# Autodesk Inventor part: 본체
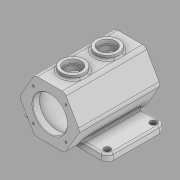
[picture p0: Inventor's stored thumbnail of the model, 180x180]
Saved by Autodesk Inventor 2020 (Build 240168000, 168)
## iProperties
Created: 2021-06
Part Number: 본체
Material: 일반
Document SubType Name: Modeling
Designer: Windows7
Density: 1 g/cm^3
Appearance: 기본값
Mass: 553.834 g
Surface Area: 1102.69 cm^2
Volume: 553.834 cm^3
Author: Windows7
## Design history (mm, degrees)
sketch "스케치1"
  geometry: L1 (75, 50)-(-75, 50); L2 (-75, 50)-(-75, -50); L3 (-75, -50)-(75, -50); L4 (75, -50)-(75, 50); L5 (75, 50)-(-75, -50); L6 (-75, 50)-(75, -50); 1 further point
  constraints: 12 end point, 2 midpoint, 2 parallel, 1 horizontal, 1 perpendicular
  dimensions: "d0" = 150 distance of L3.end L2.end; "d1" = 100 distance of L2.end L1.end
extrude "돌출1" new body sketch "스케치1" distance "d2" = 12; taper "d3" = 0 deg
node "작업 평면1"
sketch "스케치2" dims "d5" = 105
  geometry: L1 (127.5, 50)-(101.25, 4.534); L2 (101.25, 4.534)-(48.75, 4.534); L3 (48.75, 4.534)-(22.5, 50); L4 (22.5, 50)-(48.75, 95.466); L5 (48.75, 95.466)-(101.25, 95.466); L6 (101.25, 95.466)-(127.5, 50); 3 further points
  constraints: 12 end point, 1 coincident, 1 horizontal alignment, 1 vertical alignment, 15 other
  dimensions: "d6" = 50 distance of point (75, 0) point (75, 50); "d7" = 45.46633 vertical distance of L5.end L1.start
extrude "돌출2" join sketch "스케치2" distance "d8" = 140; taper "d9" = 0 deg
sketch "스케치4"
  geometry: L1 (50, 75)-(4.534, 75) reference; L2 (50, 75)-(50, -65); L3 (20, 75)-(20, 63); L4 (20, 63)-(12.5, 63); L5 (12.5, 63)-(12.5, -53); L6 (12, 50)-(12, -50) reference; L7 (12.5, -53)-(20, -53); L8 (20, -53)-(20, -65); 3 further points; 1 other entity
  constraints: 12 end point, 3 perpendicular, 2 vertical, 1 parallel, 1 point on line, 2 other
  dimensions: "d11" = 60 diameter of L3 L2; "d12" = 75 diameter of L5 L2; "d13" = 60 diameter of L8 L2; "d14" = 12 distance of L3.start L3.end; "d15" = 12 distance of L7.end L8.end
revolve "회전1" sketch "스케치4" stored, may be unused: angle "d16" = 90 deg
node "작업 평면4"
sketch "스케치6"
  geometry: L1 (26.25, 75)-(-26.25, 75) reference; C1 r 20 at (0, 35); C2 r 20 at (0, -25); 1 further point
  constraints: 2 centre point, 2 vertical alignment
  dimensions: "d22" = 40 diameter of C1; "d23" = 40 diameter of C2; "d25" = 40 distance from line of C1.centre L1; "d26" = 60 distance of C2.centre C1.centre
extrude "돌출3" join sketch "스케치6" stored distance "d27" = 140; taper "d28" = 0 deg
sketch "스케치7"
  geometry: C1 r 20 at (0, 0) reference; C2 r 20 at (0, 60) reference; 3 further points
  constraints: 2 coincident
hole "구멍1" sketch "스케치7" at (0, 60), (0, 0) diameter "d29" = 25; stored, may be unused: countersink angle "d33" = 90 deg, drill point angle "d35" = 118 deg; dims "d30" = 6, "d31" = 30, "d32" = 8, "d34" = 30
sketch "스케치8"
  geometry: L1 (75, 50)-(75, 90); L2 (75, 50)-(46.716, 78.284); C1 r 37.5 at (75, 50) reference; A1 r 40 centre (75, 50) between (75, 90) and (46.716, 78.284); 5 further points
  constraints: 4 end point, 2 coincident, 2 point on circle, 1 centre point, 1 vertical, 5 other
  dimensions: "d36" = 80 diameter of A1; "d37" = 45 deg angle of L1 L2; "d40" = 360 deg dimension on L1.start point (46.716, 78.284) (derived)
hole "구멍2" sketch "스케치8" at (46.716, 78.284), (46.716, 21.716), (103.284, 21.716), (103.284, 78.284) diameter "d42" = 3.45873; stored, may be unused: countersink angle "d46" = 90 deg, drill point angle "d48" = 118 deg; dims "d43" = 8, "d44" = 30, "d45" = 8, "d47" = 10
sketch "스케치9" dims "d49" = 80
  geometry: L1 (-75, 50)-(-75, 90); C1 r 30 at (-75, 50) reference; 5 further points
  constraints: 2 coincident, 2 end point, 1 vertical, 1 vertical alignment, 7 other
  dimensions: "d52" = 360 deg dimension on L1.start point (-75, 90) (derived)
hole "구멍3" sketch "스케치9" at (-75, 90), (-115, 50), (-75, 10), (-35, 50) diameter "d54" = 3.45873; stored, may be unused: countersink angle "d58" = 90 deg, drill point angle "d60" = 118 deg; dims "d55" = 8, "d56" = 30, "d57" = 8, "d59" = 10
fillet "모깎기1" dims "d61" = 10
sketch "스케치10"
  geometry: L1 (65, 50)-(-65, 50) reference; L2 (75, -40)-(75, 40) reference; L3 (-65, -50)-(65, -50) reference; L4 (-75, 40)-(-75, -40) reference; A1 r 10 centre (-65, 40) between (-65, 50) and (-75, 40) reference; A2 r 10 centre (65, 40) between (75, 40) and (65, 50) reference; A3 r 10 centre (65, -40) between (65, -50) and (75, -40) reference; A4 r 10 centre (-65, -40) between (-75, -40) and (-65, -50) reference; 5 further points
  constraints: 4 coincident
hole "구멍4" sketch "스케치10" at (65, 40), (65, -40), (-65, -40), (-65, 40) diameter "d62" = 11; stored, may be unused: countersink angle "d66" = 90 deg, drill point angle "d68" = 118 deg; dims "d63" = 8, "d64" = 30, "d65" = 8, "d67" = 10
fillet "모깎기2" dims "d69" = 3
fillet "모깎기3" dims "d70" = 8
fillet "모깎기4" dims "d71" = 3
fillet "모깎기5" dims "d72" = 3
chamfer "모따기1" distance "d73" = 1; stored, may be unused: second distance "d74" = 2, angle "d75" = 45 deg
fillet "모깎기6" dims "d76" = 5
sketch "스케치11"
  geometry: L1 (65, 50)-(-65, 50) reference; L2 (75, -40)-(75, 40) reference; L3 (-65, -50)-(65, -50) reference; L4 (-75, 40)-(-75, -40) reference; L5 (-57.998, 20.739)-(-57.998, -20.739); L6 (-57.998, -20.739)-(-64.002, -20.739); L7 (-64.002, -20.739)-(-64.002, 20.739); L8 (-64.002, 20.739)-(-57.998, 20.739); L9 (-57.998, 20.739)-(-64.002, -20.739); C1 r 5.5 at (-65, -40) reference; C2 r 5.5 at (65, 40) reference; C3 r 5.5 at (65, -40) reference; C4 r 5.5 at (-65, 40) reference; A1 r 10 centre (-65, 40) between (-65, 50) and (-75, 40) reference; A2 r 10 centre (65, 40) between (75, 40) and (65, 50) reference; A3 r 10 centre (65, -40) between (65, -50) and (75, -40) reference; A4 r 10 centre (-65, -40) between (-75, -40) and (-65, -50) reference; 2 further points
  constraints: 2 end point, 1 midpoint, 2 other
  dimensions: "d77" = 50 distance from line of L1 point (-61, 0); "d78" = 14 distance from line of L4 point (-61, 0)
feature "엠보싱1" sketch "스케치11" dims "d79" = 0.5, "d80" = 0
node "솔리드1"
node "투영된 루프1"
node "투영된 루프2"
node "투영된 루프3"
node "투영된 루프4"
feature "A9D066F2-1C7D-4E18-AEED-F7BC21143FA4" dims "d62" = 11, "d63" = 8, "d64" = 30, "d65" = 8, "d66" = 90 deg, "d67" = 10, "d68" = 118 deg
other parameters: "d4" = 25, "d21" = -102.5
